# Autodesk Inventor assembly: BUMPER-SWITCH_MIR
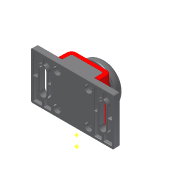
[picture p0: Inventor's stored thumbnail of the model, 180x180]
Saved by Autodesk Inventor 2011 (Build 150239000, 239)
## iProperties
Created: 2007-08
Part Number: BUMPER-SWITCH_MIR
Document SubType Name: Assembly
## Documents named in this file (5)
- C:\Data Folder\VEX 2011\Inventor Datasets\Unit 16\Components\BUMPER-SWITCH_MIR.iam
- C:\Data Folder\VEX 2011\Inventor Datasets\Unit 16\Components\BUMPER-SWITCH-TOP_MIR.ipt
- C:\Data Folder\VEX 2011\Inventor Datasets\Unit 16\Components\BUMPER-SWITCH-BOT_MIR.ipt
- C:\Data Folder\VEX 2011\Inventor Datasets\Unit 16\Components\BUMPER-SWITCH-INNER-HEAD_MIR.ipt
- C:\Data Folder\VEX 2011\Inventor Datasets\Unit 16\Components\BUMPER-SWITCH-HEAD_MIR.ipt
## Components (4 placed, 4 different names)
1. BUMPER-SWITCH-TOP_MIR:1
2. BUMPER-SWITCH-BOT_MIR:1
3. BUMPER-SWITCH-INNER-HEAD_MIR:1
4. BUMPER-SWITCH-HEAD_MIR:1
